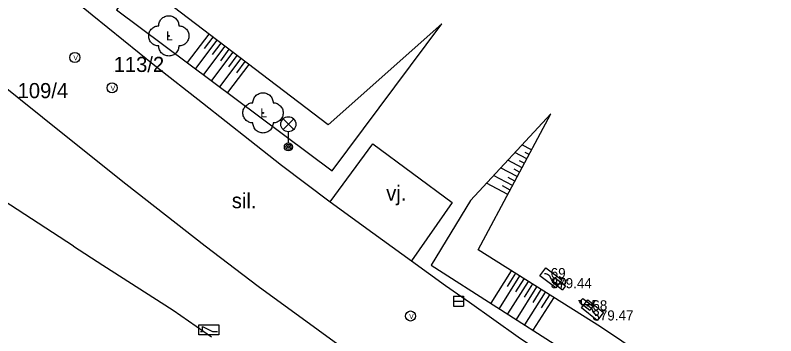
# Model space of a CAD drawing. Extents: x -836568 to -836015, y -1070547 to -1070212.
# Drawn here: x -836460.84 to -836423.06, y -1070365.29 to -1070349.39 of the extents above; entities that cross this region are included whole.
import ezdxf

# ---------------------------------------------------------------- set-up
doc = ezdxf.new("R2010")
doc.units = 0
for name, color, linetype in [('BodPole_mer', 7, 'Continuous'), ('BodPole_popis', 7, 'Continuous'), ('Doprava_hranice', 7, 'Continuous'), ('Doprava_kody', 7, 'Continuous'), ('PovrZnIS_body', 7, 'Continuous'), ('PovrZnIS_hranice', 7, 'Continuous'), ('PovrZnIS_kody', 7, 'Continuous'), ('RuianPar_popis', 7, 'Continuous'), ('Stavby_linie', 7, 'Continuous'), ('Vyskopis_linie', 7, 'Continuous'), ('Zelen_body', 7, 'Continuous')]:
    doc.layers.add(name, color=color, linetype=linetype)

msp = doc.modelspace()

# ---------------------------------------------------------------- linework, layer by layer
at = {"layer": 'BodPole_mer'}
for p, q in [((-836439.64, -1070349.82), (-836439.64, -1070349.82)), ((-836453.21, -1070350.41), (-836453.21, -1070350.41)), ((-836457.88, -1070351.48), (-836457.88, -1070351.48)), ((-836453.9, -1070351.88), (-836453.9, -1070351.88)), ((-836456.03, -1070352.99), (-836456.03, -1070352.99)), ((-836451.54, -1070353.74), (-836451.54, -1070353.74)), ((-836448.53, -1070354.23), (-836448.53, -1070354.23)), ((-836434.23, -1070354.27), (-836434.23, -1070354.27)), ((-836445.29, -1070354.83), (-836445.29, -1070354.83)), ((-836458.47, -1070355.27), (-836458.47, -1070355.27)), ((-836449.19, -1070355.59), (-836449.19, -1070355.59)), ((-836443.08, -1070355.77), (-836443.08, -1070355.77)), ((-836447.27, -1070355.92), (-836447.27, -1070355.92)), ((-836447.61, -1070356.83), (-836447.61, -1070356.83)), ((-836445.09, -1070357.11), (-836445.09, -1070357.11)), ((-836455.35, -1070357.76), (-836455.35, -1070357.76)), ((-836445.19, -1070358.65), (-836445.19, -1070358.65)), ((-836439.13, -1070358.68), (-836439.13, -1070358.68)), ((-836438.23, -1070358.57), (-836438.23, -1070358.57)), ((-836443.08, -1070360.18), (-836443.08, -1070360.18)), ((-836457.94, -1070360.84), (-836457.94, -1070360.84)), ((-836457.94, -1070360.84), (-836457.94, -1070360.84)), ((-836451.4, -1070360.84), (-836451.4, -1070360.84)), ((-836437.84, -1070361.03), (-836437.84, -1070361.03)), ((-836456.49, -1070361.78), (-836456.49, -1070361.78)), ((-836441.15, -1070361.58), (-836441.15, -1070361.58)), ((-836440.17, -1070361.78), (-836440.17, -1070361.78)), ((-836434.24, -1070362.43), (-836434.24, -1070362.43)), ((-836434.01, -1070362.42), (-836434.01, -1070362.42)), ((-836434.01, -1070362.42), (-836434.01, -1070362.42)), ((-836448.77, -1070362.84), (-836448.77, -1070362.84)), ((-836439.46, -1070362.8), (-836439.46, -1070362.8)), ((-836434.16, -1070362.62), (-836434.16, -1070362.62)), ((-836434.16, -1070362.62), (-836434.16, -1070362.62)), ((-836433.5, -1070362.81), (-836433.5, -1070362.81)), ((-836433.5, -1070362.81), (-836433.5, -1070362.81)), ((-836433.66, -1070363.01), (-836433.66, -1070363.01)), ((-836433.66, -1070363.01), (-836433.66, -1070363.01)), ((-836438.82, -1070363.57), (-836438.82, -1070363.57)), ((-836438.28, -1070363.63), (-836438.28, -1070363.63)), ((-836432.8, -1070363.63), (-836432.8, -1070363.63)), ((-836432.8, -1070363.63), (-836432.8, -1070363.63)), ((-836432.64, -1070363.44), (-836432.64, -1070363.44)), ((-836432.64, -1070363.44), (-836432.64, -1070363.44)), ((-836452.99, -1070364.02), (-836452.99, -1070364.02)), ((-836432.3, -1070364.02), (-836432.3, -1070364.02)), ((-836432.3, -1070364.02), (-836432.3, -1070364.02)), ((-836432.17, -1070364.03), (-836432.17, -1070364.03)), ((-836432.15, -1070363.82), (-836432.15, -1070363.82)), ((-836432.15, -1070363.82), (-836432.15, -1070363.82)), ((-836441.2, -1070364.31), (-836441.2, -1070364.31)), ((-836431.77, -1070364.85), (-836431.77, -1070364.85)), ((-836451.22, -1070365), (-836451.22, -1070365)), ((-836451.22, -1070365), (-836451.22, -1070365)), ((-836445.79, -1070365.02), (-836445.79, -1070365.02))]:
    msp.add_line(p, q, dxfattribs=at)
at = {"layer": 'Doprava_hranice'}
for points in [[(-836486.04, -1070295.25), (-836491.51, -1070301.7), (-836496.11, -1070306.84), (-836497.41, -1070308.37), (-836498.02, -1070309.18), (-836498.47, -1070310.1), (-836498.73, -1070311.08), (-836498.85, -1070312.07), (-836498.78, -1070313.12), (-836498.51, -1070314.1), (-836498.1, -1070315.03), (-836497.52, -1070315.85), (-836497.01, -1070316.45), (-836496.48, -1070317), (-836489.02, -1070323.12), (-836476.76, -1070333.19), (-836472.89, -1070336.35), (-836460.9, -1070346.19), (-836457.02, -1070349.36), (-836453.9, -1070351.88), (-836451.54, -1070353.74), (-836449.19, -1070355.59), (-836447.61, -1070356.83), (-836445.19, -1070358.65)], [(-836422.05, -1070380.7), (-836424.17, -1070379.44), (-836425.85, -1070378.38), (-836427.55, -1070377.33), (-836430.1, -1070375.74), (-836432.62, -1070374.1), (-836435.14, -1070372.46), (-836437.61, -1070370.78), (-836438.47, -1070370.23), (-836440.92, -1070368.5), (-836443.36, -1070366.79), (-836445.79, -1070365.02), (-836448.77, -1070362.84), (-836451.4, -1070360.84), (-836455.35, -1070357.76), (-836458.47, -1070355.27), (-836461.58, -1070352.77)], [(-836445.19, -1070358.65), (-836443.08, -1070355.77), (-836439.13, -1070358.68), (-836441.15, -1070361.58)], [(-836445.19, -1070358.65), (-836443.08, -1070360.18), (-836441.15, -1070361.58), (-836439.46, -1070362.8), (-836438.28, -1070363.63), (-836435.85, -1070365.34), (-836433.37, -1070367.02), (-836430.87, -1070368.7), (-836428.32, -1070370.32), (-836425.77, -1070371.95), (-836423.24, -1070373.54), (-836420.69, -1070375.11)]]:
    msp.add_lwpolyline(points, dxfattribs=at)
at = {"layer": 'PovrZnIS_body'}
for p, q in [((-836447.535, -1070355.06), (-836447.005, -1070354.53)), ((-836447.535, -1070354.53), (-836447.005, -1070355.06)), ((-836447.27, -1070355.72), (-836447.27, -1070355.17)), ((-836434.786, -1070362.315), (-836434.485, -1070361.917)), ((-836434.485, -1070361.917), (-836433.687, -1070362.52)), ((-836433.989, -1070362.919), (-836434.786, -1070362.315)), ((-836433.687, -1070362.52), (-836433.989, -1070362.919)), ((-836439.07, -1070363.32), (-836438.57, -1070363.32)), ((-836439.07, -1070363.32), (-836439.07, -1070363.82)), ((-836438.57, -1070363.32), (-836438.57, -1070363.82)), ((-836439.07, -1070363.57), (-836438.57, -1070363.57)), ((-836432.713, -1070363.901), (-836432.401, -1070363.51)), ((-836432.401, -1070363.51), (-836431.62, -1070364.135)), ((-836439.07, -1070363.82), (-836438.57, -1070363.82)), ((-836431.932, -1070364.525), (-836432.713, -1070363.901)), ((-836431.62, -1070364.135), (-836431.932, -1070364.525)), ((-836451.72, -1070364.751), (-836450.72, -1070364.749)), ((-836451.72, -1070364.751), (-836450.72, -1070364.749)), ((-836451.72, -1070365.251), (-836451.72, -1070364.751)), ((-836451.72, -1070365.251), (-836451.72, -1070364.751)), ((-836451.531, -1070365.085), (-836451.531, -1070364.835)), ((-836451.531, -1070364.835), (-836451.031, -1070365.084)), ((-836451.531, -1070365.085), (-836451.531, -1070364.835)), ((-836451.531, -1070364.835), (-836451.031, -1070365.084)), ((-836450.72, -1070364.749), (-836450.72, -1070365.249)), ((-836450.72, -1070364.749), (-836450.72, -1070365.249)), ((-836451.641, -1070365.085), (-836451.531, -1070365.085)), ((-836451.641, -1070365.085), (-836451.531, -1070365.085)), ((-836451.031, -1070365.084), (-836450.786, -1070365.083)), ((-836451.031, -1070365.084), (-836450.786, -1070365.083)), ((-836450.72, -1070365.249), (-836451.72, -1070365.251)), ((-836450.72, -1070365.249), (-836451.72, -1070365.251))]:
    msp.add_line(p, q, dxfattribs=at)
for points in [[(-836434.54, -1070362.203), (-836434.492, -1070362.207), (-836434.444, -1070362.219), (-836434.396, -1070362.239), (-836434.352, -1070362.266), (-836434.314, -1070362.301), (-836434.281, -1070362.341), (-836434.257, -1070362.385), (-836434.24, -1070362.43)], [(-836434.24, -1070362.43), (-836434.223, -1070362.475), (-836434.199, -1070362.518), (-836434.167, -1070362.558), (-836434.128, -1070362.593), (-836434.084, -1070362.621), (-836434.037, -1070362.641), (-836433.989, -1070362.652), (-836433.941, -1070362.656)], [(-836432.464, -1070363.795), (-836432.416, -1070363.8), (-836432.368, -1070363.813), (-836432.321, -1070363.834), (-836432.278, -1070363.863), (-836432.24, -1070363.899), (-836432.209, -1070363.94), (-836432.186, -1070363.984), (-836432.17, -1070364.03)], [(-836432.17, -1070364.03), (-836432.154, -1070364.075), (-836432.131, -1070364.119), (-836432.1, -1070364.16), (-836432.063, -1070364.196), (-836432.02, -1070364.225), (-836431.973, -1070364.246), (-836431.925, -1070364.259), (-836431.877, -1070364.264)]]:
    msp.add_lwpolyline(points, dxfattribs=at)
for centre in [(-836457.88, -1070351.48), (-836456.03, -1070352.99), (-836441.2, -1070364.31)]:
    msp.add_circle(centre, 0.25, dxfattribs=at)
for centre, major_axis in [((-836447.27, -1070354.795), (0.375, 0)), ((-836447.27, -1070355.92), (0.2, 0)), ((-836447.266, -1070355.92), (0.125, 0)), ((-836447.266, -1070355.92), (0.05, 0))]:
    msp.add_ellipse(centre, major_axis=major_axis, ratio=0.999998, dxfattribs=at)
at = {"layer": 'PovrZnIS_hranice'}
for p, q in [((-836434.16, -1070362.62), (-836433.66, -1070363.01)), ((-836434.16, -1070362.62), (-836433.66, -1070363.01)), ((-836432.8, -1070363.63), (-836432.3, -1070364.02)), ((-836432.8, -1070363.63), (-836432.3, -1070364.02))]:
    msp.add_line(p, q, dxfattribs=at)
for points in [[(-836434.16, -1070362.62), (-836434.01, -1070362.42), (-836433.5, -1070362.81), (-836433.66, -1070363.01)], [(-836434.16, -1070362.62), (-836434.01, -1070362.42), (-836433.5, -1070362.81), (-836433.66, -1070363.01)], [(-836432.8, -1070363.63), (-836432.64, -1070363.44), (-836432.15, -1070363.82), (-836432.3, -1070364.02)], [(-836432.8, -1070363.63), (-836432.64, -1070363.44), (-836432.15, -1070363.82), (-836432.3, -1070364.02)]]:
    msp.add_lwpolyline(points, dxfattribs=at)
at = {"layer": 'PovrZnIS_kody'}
for p, q in [((-836434.221, -1070362.52), (-836434.1, -1070362.52)), ((-836434.221, -1070362.52), (-836434.1, -1070362.52)), ((-836434.1, -1070362.52), (-836434.1, -1070362.72)), ((-836434.1, -1070362.52), (-836434.1, -1070362.72)), ((-836433.5, -1070362.72), (-836433.5, -1070362.52)), ((-836433.5, -1070362.52), (-836433.366, -1070362.52)), ((-836433.5, -1070362.72), (-836433.5, -1070362.52)), ((-836433.5, -1070362.52), (-836433.366, -1070362.52)), ((-836434.1, -1070362.72), (-836433.5, -1070362.72)), ((-836434.1, -1070362.72), (-836433.5, -1070362.72)), ((-836432.851, -1070363.54), (-836432.73, -1070363.54)), ((-836432.851, -1070363.54), (-836432.73, -1070363.54)), ((-836432.73, -1070363.54), (-836432.73, -1070363.74)), ((-836432.73, -1070363.54), (-836432.73, -1070363.74)), ((-836432.13, -1070363.74), (-836432.13, -1070363.54)), ((-836432.13, -1070363.54), (-836431.996, -1070363.54)), ((-836432.13, -1070363.74), (-836432.13, -1070363.54)), ((-836432.13, -1070363.54), (-836431.996, -1070363.54)), ((-836432.73, -1070363.74), (-836432.13, -1070363.74)), ((-836432.73, -1070363.74), (-836432.13, -1070363.74))]:
    msp.add_line(p, q, dxfattribs=at)
at = {"layer": 'RuianPar_popis'}
for p, q in [((-836455.95, -1070352.2), (-836455.95, -1070352.2)), ((-836460.72, -1070353.5), (-836460.72, -1070353.5))]:
    msp.add_line(p, q, dxfattribs=at)
at = {"layer": 'Stavby_linie'}
for p, q in [((-836457.94, -1070360.84), (-836456.49, -1070361.78)), ((-836457.94, -1070360.84), (-836456.49, -1070361.78)), ((-836456.49, -1070361.78), (-836452.99, -1070364.02)), ((-836452.99, -1070364.02), (-836451.09, -1070365.35))]:
    msp.add_line(p, q, dxfattribs=at)
msp.add_lwpolyline([(-836457.94, -1070360.84), (-836463.18, -1070357.45), (-836463.65, -1070357.11), (-836464.69, -1070356.37)], dxfattribs=at)
at = {"layer": 'Vyskopis_linie'}
for p, q in [((-836451.22, -1070350.32), (-836452.29, -1070351.73)), ((-836451.02, -1070350.47), (-836451.45, -1070351.03)), ((-836450.82, -1070350.62), (-836451.89, -1070352.03)), ((-836450.62, -1070350.77), (-836451.05, -1070351.33)), ((-836450.42, -1070350.92), (-836451.49, -1070352.33)), ((-836450.03, -1070351.22), (-836451.09, -1070352.63)), ((-836450.22, -1070351.07), (-836450.65, -1070351.64)), ((-836449.63, -1070351.53), (-836450.69, -1070352.93)), ((-836449.83, -1070351.38), (-836450.25, -1070351.94)), ((-836449.23, -1070351.83), (-836450.29, -1070353.22)), ((-836449.43, -1070351.68), (-836449.85, -1070352.24)), ((-836435.19, -1070356.07), (-836435.67, -1070355.82)), ((-836435.43, -1070356.51), (-836436.02, -1070356.2)), ((-836435.31, -1070356.29), (-836435.5, -1070356.19)), ((-836435.66, -1070356.95), (-836436.37, -1070356.57)), ((-836435.55, -1070356.73), (-836435.78, -1070356.61)), ((-836435.9, -1070357.39), (-836436.73, -1070356.95)), ((-836435.78, -1070357.17), (-836436.06, -1070357.02)), ((-836436.13, -1070357.84), (-836437.08, -1070357.33)), ((-836436.02, -1070357.62), (-836436.35, -1070357.44)), ((-836436.37, -1070358.28), (-836437.43, -1070357.71)), ((-836436.25, -1070358.06), (-836436.63, -1070357.85)), ((-836436.21, -1070362.06), (-836437.22, -1070363.67)), ((-836435.99, -1070362.19), (-836436.4, -1070362.84)), ((-836435.78, -1070362.32), (-836436.8, -1070363.94)), ((-836435.36, -1070362.59), (-836436.38, -1070364.21)), ((-836435.57, -1070362.46), (-836435.98, -1070363.11)), ((-836434.94, -1070362.86), (-836435.96, -1070364.48)), ((-836435.15, -1070362.72), (-836435.56, -1070363.37)), ((-836434.51, -1070363.12), (-836435.54, -1070364.75)), ((-836434.73, -1070362.99), (-836435.13, -1070363.64)), ((-836434.3, -1070363.26), (-836434.71, -1070363.91)), ((-836434.09, -1070363.39), (-836435.12, -1070365.02))]:
    msp.add_line(p, q, dxfattribs=at)
for points in [[(-836448.31, -1070340.28), (-836448.91, -1070340.09), (-836455.8, -1070349.11), (-836445.09, -1070357.11), (-836439.64, -1070349.82)], [(-836439.64, -1070349.82), (-836445.29, -1070354.83), (-836453.34, -1070348.7), (-836448.31, -1070340.28)], [(-836434.23, -1070354.27), (-836438.23, -1070358.57), (-836440.17, -1070361.78), (-836433.66, -1070365.96), (-836425.36, -1070371.19), (-836413.35, -1070378.34), (-836408.55, -1070381.18), (-836406.45, -1070381.27), (-836403.31, -1070376.81), (-836398.57, -1070364.21), (-836395.25, -1070356.24), (-836395.84, -1070356.16)], [(-836395.84, -1070356.16), (-836401.02, -1070368.01), (-836403.57, -1070374.4), (-836406.76, -1070379.93), (-836408.49, -1070379.57), (-836416.6, -1070374.24), (-836425.3, -1070369.18), (-836431.77, -1070364.85), (-836437.84, -1070361.03), (-836434.23, -1070354.27)]]:
    msp.add_lwpolyline(points, dxfattribs=at)
at = {"layer": 'Zelen_body'}
for p, q in [((-836453.21, -1070350.41), (-836453.21, -1070350.41)), ((-836448.53, -1070354.23), (-836448.53, -1070354.23))]:
    msp.add_line(p, q, dxfattribs=at)
for points in [[(-836453.71, -1070349.91), (-836453.708, -1070349.862), (-836453.7, -1070349.813), (-836453.688, -1070349.763), (-836453.67, -1070349.714), (-836453.646, -1070349.665), (-836453.617, -1070349.619), (-836453.583, -1070349.576), (-836453.544, -1070349.537), (-836453.501, -1070349.503), (-836453.455, -1070349.474), (-836453.406, -1070349.45), (-836453.357, -1070349.432), (-836453.307, -1070349.42), (-836453.258, -1070349.412), (-836453.21, -1070349.41), (-836453.162, -1070349.412), (-836453.113, -1070349.42), (-836453.063, -1070349.432), (-836453.014, -1070349.45), (-836452.965, -1070349.474), (-836452.919, -1070349.503), (-836452.876, -1070349.537), (-836452.837, -1070349.576), (-836452.803, -1070349.619), (-836452.774, -1070349.665), (-836452.75, -1070349.714), (-836452.732, -1070349.763), (-836452.72, -1070349.813), (-836452.712, -1070349.862), (-836452.71, -1070349.91)], [(-836453.71, -1070350.91), (-836453.758, -1070350.908), (-836453.807, -1070350.9), (-836453.857, -1070350.888), (-836453.906, -1070350.87), (-836453.955, -1070350.846), (-836454.001, -1070350.817), (-836454.044, -1070350.783), (-836454.083, -1070350.744), (-836454.117, -1070350.701), (-836454.146, -1070350.655), (-836454.17, -1070350.606), (-836454.188, -1070350.557), (-836454.2, -1070350.507), (-836454.208, -1070350.458), (-836454.21, -1070350.41), (-836454.208, -1070350.362), (-836454.2, -1070350.313), (-836454.188, -1070350.263), (-836454.17, -1070350.214), (-836454.146, -1070350.165), (-836454.117, -1070350.119), (-836454.083, -1070350.076), (-836454.044, -1070350.037), (-836454.001, -1070350.003), (-836453.955, -1070349.974), (-836453.906, -1070349.95), (-836453.857, -1070349.932), (-836453.807, -1070349.92), (-836453.758, -1070349.912), (-836453.71, -1070349.91)], [(-836452.71, -1070349.91), (-836452.662, -1070349.912), (-836452.613, -1070349.92), (-836452.563, -1070349.932), (-836452.514, -1070349.95), (-836452.465, -1070349.974), (-836452.419, -1070350.003), (-836452.376, -1070350.037), (-836452.337, -1070350.076), (-836452.303, -1070350.119), (-836452.274, -1070350.165), (-836452.25, -1070350.214), (-836452.232, -1070350.263), (-836452.22, -1070350.313), (-836452.212, -1070350.362), (-836452.21, -1070350.41), (-836452.212, -1070350.458), (-836452.22, -1070350.507), (-836452.232, -1070350.557), (-836452.25, -1070350.606), (-836452.274, -1070350.655), (-836452.303, -1070350.701), (-836452.337, -1070350.744), (-836452.376, -1070350.783), (-836452.419, -1070350.817), (-836452.465, -1070350.846), (-836452.514, -1070350.87), (-836452.563, -1070350.888), (-836452.613, -1070350.9), (-836452.662, -1070350.908), (-836452.71, -1070350.91)], [(-836452.71, -1070350.91), (-836452.712, -1070350.958), (-836452.72, -1070351.007), (-836452.732, -1070351.057), (-836452.75, -1070351.106), (-836452.774, -1070351.155), (-836452.803, -1070351.201), (-836452.837, -1070351.244), (-836452.876, -1070351.283), (-836452.919, -1070351.317), (-836452.965, -1070351.346), (-836453.014, -1070351.37), (-836453.063, -1070351.388), (-836453.113, -1070351.4), (-836453.162, -1070351.408), (-836453.21, -1070351.41), (-836453.258, -1070351.408), (-836453.307, -1070351.4), (-836453.357, -1070351.388), (-836453.406, -1070351.37), (-836453.455, -1070351.346), (-836453.501, -1070351.317), (-836453.544, -1070351.283), (-836453.583, -1070351.244), (-836453.617, -1070351.201), (-836453.646, -1070351.155), (-836453.67, -1070351.106), (-836453.688, -1070351.057), (-836453.7, -1070351.007), (-836453.708, -1070350.958), (-836453.71, -1070350.91)], [(-836449.03, -1070353.73), (-836449.028, -1070353.682), (-836449.02, -1070353.633), (-836449.008, -1070353.583), (-836448.99, -1070353.534), (-836448.966, -1070353.485), (-836448.937, -1070353.439), (-836448.903, -1070353.396), (-836448.864, -1070353.357), (-836448.821, -1070353.323), (-836448.775, -1070353.294), (-836448.726, -1070353.27), (-836448.677, -1070353.252), (-836448.627, -1070353.24), (-836448.578, -1070353.232), (-836448.53, -1070353.23), (-836448.482, -1070353.232), (-836448.433, -1070353.24), (-836448.383, -1070353.252), (-836448.334, -1070353.27), (-836448.285, -1070353.294), (-836448.239, -1070353.323), (-836448.196, -1070353.357), (-836448.157, -1070353.396), (-836448.123, -1070353.439), (-836448.094, -1070353.485), (-836448.07, -1070353.534), (-836448.052, -1070353.583), (-836448.04, -1070353.633), (-836448.032, -1070353.682), (-836448.03, -1070353.73)], [(-836449.03, -1070354.73), (-836449.078, -1070354.728), (-836449.127, -1070354.72), (-836449.177, -1070354.708), (-836449.226, -1070354.69), (-836449.275, -1070354.666), (-836449.321, -1070354.637), (-836449.364, -1070354.603), (-836449.403, -1070354.564), (-836449.437, -1070354.521), (-836449.466, -1070354.475), (-836449.49, -1070354.426), (-836449.508, -1070354.377), (-836449.52, -1070354.327), (-836449.528, -1070354.278), (-836449.53, -1070354.23), (-836449.528, -1070354.182), (-836449.52, -1070354.133), (-836449.508, -1070354.083), (-836449.49, -1070354.034), (-836449.466, -1070353.985), (-836449.437, -1070353.939), (-836449.403, -1070353.896), (-836449.364, -1070353.857), (-836449.321, -1070353.823), (-836449.275, -1070353.794), (-836449.226, -1070353.77), (-836449.177, -1070353.752), (-836449.127, -1070353.74), (-836449.078, -1070353.732), (-836449.03, -1070353.73)], [(-836448.03, -1070353.73), (-836447.982, -1070353.732), (-836447.933, -1070353.74), (-836447.883, -1070353.752), (-836447.834, -1070353.77), (-836447.785, -1070353.794), (-836447.739, -1070353.823), (-836447.696, -1070353.857), (-836447.657, -1070353.896), (-836447.623, -1070353.939), (-836447.594, -1070353.985), (-836447.57, -1070354.034), (-836447.552, -1070354.083), (-836447.54, -1070354.133), (-836447.532, -1070354.182), (-836447.53, -1070354.23), (-836447.532, -1070354.278), (-836447.54, -1070354.327), (-836447.552, -1070354.377), (-836447.57, -1070354.426), (-836447.594, -1070354.475), (-836447.623, -1070354.521), (-836447.657, -1070354.564), (-836447.696, -1070354.603), (-836447.739, -1070354.637), (-836447.785, -1070354.666), (-836447.834, -1070354.69), (-836447.883, -1070354.708), (-836447.933, -1070354.72), (-836447.982, -1070354.728), (-836448.03, -1070354.73)], [(-836448.03, -1070354.73), (-836448.032, -1070354.778), (-836448.04, -1070354.827), (-836448.052, -1070354.877), (-836448.07, -1070354.926), (-836448.094, -1070354.975), (-836448.123, -1070355.021), (-836448.157, -1070355.064), (-836448.196, -1070355.103), (-836448.239, -1070355.137), (-836448.285, -1070355.166), (-836448.334, -1070355.19), (-836448.383, -1070355.208), (-836448.433, -1070355.22), (-836448.482, -1070355.228), (-836448.53, -1070355.23), (-836448.578, -1070355.228), (-836448.627, -1070355.22), (-836448.677, -1070355.208), (-836448.726, -1070355.19), (-836448.775, -1070355.166), (-836448.821, -1070355.137), (-836448.864, -1070355.103), (-836448.903, -1070355.064), (-836448.937, -1070355.021), (-836448.966, -1070354.975), (-836448.99, -1070354.926), (-836449.008, -1070354.877), (-836449.02, -1070354.827), (-836449.028, -1070354.778), (-836449.03, -1070354.73)]]:
    msp.add_lwpolyline(points, dxfattribs=at)
for centre in [(-836453.21, -1070350.41), (-836448.53, -1070354.23)]:
    msp.add_ellipse(centre, major_axis=(0.025, 0), ratio=0.999997, dxfattribs=at)

# ---------------------------------------------------------------- texts
at = {"layer": 'BodPole_popis'}
for s, p in [('69', (-836434.24, -1070362.43)), ('379.44', (-836434.24, -1070362.93)), ('68', (-836432.17, -1070364.03)), ('379.47', (-836432.17, -1070364.53))]:
    msp.add_text(s, height=0.5, dxfattribs=at).set_placement(p)
at = {"layer": 'Doprava_kody'}
for s, p in [('vj.', (-836442.41, -1070358.59)), ('sil.', (-836450.08, -1070358.96))]:
    msp.add_text(s, height=0.75, dxfattribs=at).set_placement(p)
at = {"layer": 'PovrZnIS_body'}
for p in [(-836457.951, -1070351.623), (-836456.101, -1070353.133), (-836441.271, -1070364.453)]:
    msp.add_text('V', height=0.25, dxfattribs=at).set_placement(p)
at = {"layer": 'RuianPar_popis'}
for s, p in [('113/2', (-836455.95, -1070352.2)), ('109/4', (-836460.72, -1070353.5))]:
    msp.add_text(s, height=0.75, dxfattribs=at).set_placement(p)
at = {"layer": 'Zelen_body'}
for p in [(-836453.341, -1070350.635), (-836448.661, -1070354.455)]:
    msp.add_text('L', height=0.45, dxfattribs=at).set_placement(p)

doc.saveas('drawing.dxf')
